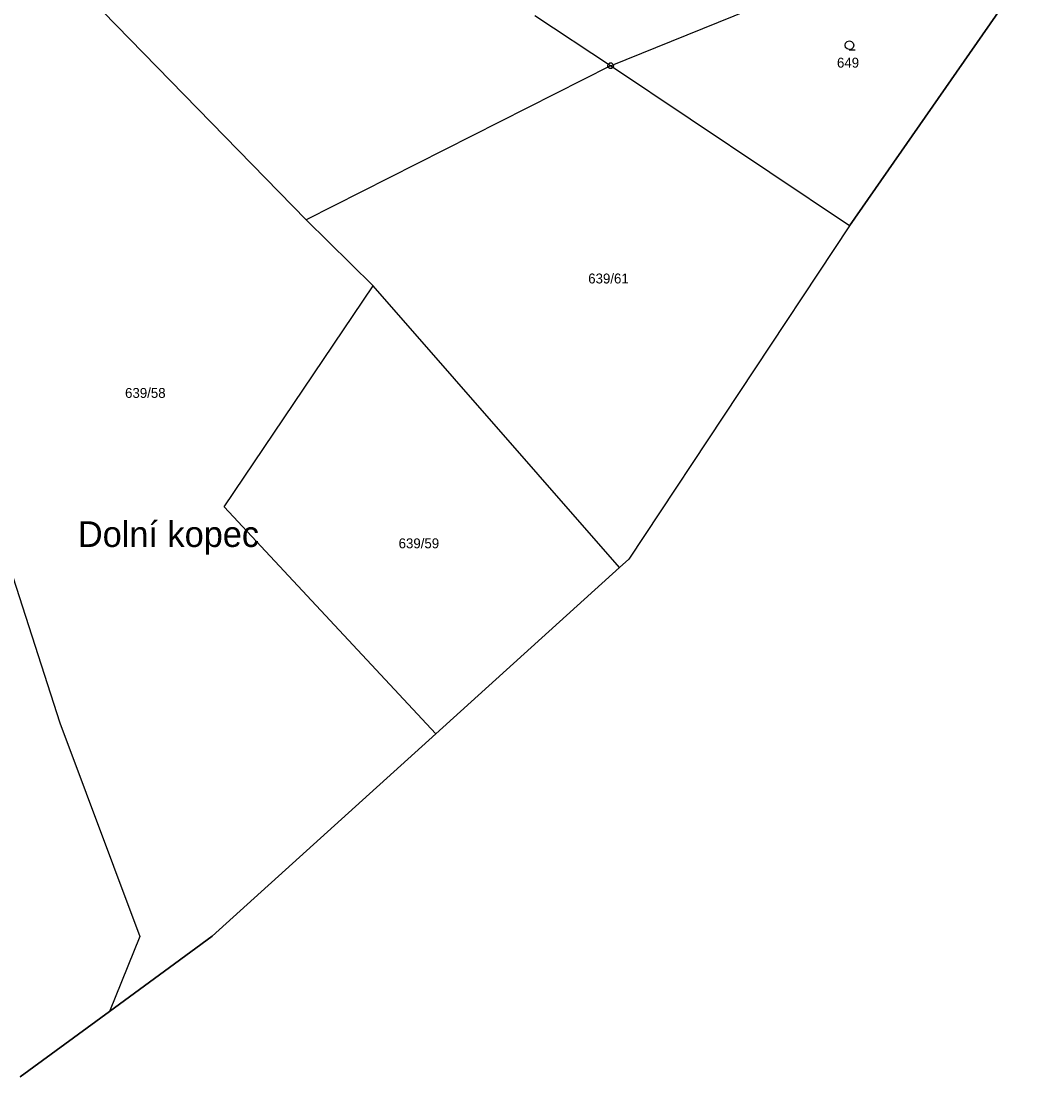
# Model space of a CAD drawing. Extents: x -759699 to -757730, y -1172308 to -1170857.
# Drawn here: x -758550 to -758376.9, y -1171577.6 to -1171396.5 of the extents above; entities that cross this region are included whole.
import ezdxf

# ---------------------------------------------------------------- set-up
doc = ezdxf.new("R2010")
doc.units = 0
for name, color, linetype in [('Vrstva 1', 7, 'Continuous'), ('Vrstva 11', 7, 'Continuous'), ('Vrstva 2', 7, 'Continuous'), ('Vrstva 3', 7, 'Continuous'), ('Vrstva 7', 7, 'Continuous'), ('Vrstva 8', 7, 'Continuous')]:
    doc.layers.add(name, color=color, linetype=linetype)

msp = doc.modelspace()

# ---------------------------------------------------------------- linework, layer by layer
at = {"layer": 'Vrstva 1'}
for p, q in [((-758501.09, -1171430.59), (-758549.8, -1171380.61)), ((-758448.84, -1171404.15), (-758397.71, -1171383.44)), ((-758407.85, -1171431.61), (-758376.92, -1171387.14)), ((-758448.84, -1171404.15), (-758461.83, -1171395.59)), ((-758448.84, -1171404.15), (-758501.09, -1171430.59)), ((-758407.85, -1171431.61), (-758448.84, -1171404.15)), ((-758501.09, -1171430.59), (-758489.58, -1171441.92)), ((-758407.85, -1171431.61), (-758445.74, -1171488.79)), ((-758515.17, -1171479.82), (-758489.58, -1171441.92)), ((-758447.31, -1171490.21), (-758489.58, -1171441.92)), ((-758562.96, -1171456.1), (-758543.32, -1171516.87)), ((-758478.81, -1171518.72), (-758515.17, -1171479.82)), ((-758447.31, -1171490.21), (-758445.74, -1171488.79)), ((-758478.81, -1171518.72), (-758447.31, -1171490.21)), ((-758543.32, -1171516.87), (-758529.61, -1171553.52)), ((-758517.19, -1171553.46), (-758478.81, -1171518.72)), ((-758529.61, -1171553.52), (-758534.83, -1171566.37)), ((-758524.54, -1171558.84), (-758517.19, -1171553.46)), ((-758534.83, -1171566.37), (-758524.54, -1171558.84)), ((-758550.16, -1171577.59), (-758534.83, -1171566.37))]:
    msp.add_line(p, q, dxfattribs=at)
at = {"layer": 'Vrstva 11'}
for p, q in [((-758376.92, -1171387.14), (-758407.85, -1171431.61)), ((-758407.85, -1171431.61), (-758445.74, -1171488.79)), ((-758445.74, -1171488.79), (-758447.31, -1171490.21)), ((-758447.31, -1171490.21), (-758478.81, -1171518.72)), ((-758478.81, -1171518.72), (-758517.19, -1171553.46)), ((-758517.19, -1171553.46), (-758524.54, -1171558.84)), ((-758524.54, -1171558.84), (-758534.83, -1171566.37)), ((-758534.83, -1171566.37), (-758550.16, -1171577.59))]:
    msp.add_line(p, q, dxfattribs=at)
at = {"layer": 'Vrstva 3'}
msp.add_lwpolyline([(-758407.88, -1171401.37), (-758408.26, -1171401.27), (-758408.53, -1171401), (-758408.63, -1171400.63), (-758408.53, -1171400.26), (-758408.26, -1171399.99), (-758407.89, -1171399.89), (-758407.52, -1171399.99), (-758407.25, -1171400.26), (-758407.15, -1171400.64), (-758407.25, -1171401.02), (-758407.52, -1171401.29), (-758407.9, -1171401.39), (-758406.9, -1171401.39)], dxfattribs=at)
at = {"layer": 'Vrstva 8'}
msp.add_line((-758448.96, -1171404.15), (-758448.72, -1171404.15), dxfattribs=at)
msp.add_lwpolyline([(-758448.69, -1171403.67), (-758448.44, -1171403.85), (-758448.34, -1171404.14), (-758448.44, -1171404.43), (-758448.69, -1171404.61), (-758449, -1171404.61), (-758449.25, -1171404.43), (-758449.35, -1171404.14), (-758449.25, -1171403.85), (-758449, -1171403.67)], close=True, dxfattribs=at)

# ---------------------------------------------------------------- texts
at = {"layer": 'Vrstva 2'}
for s, p in [('649', (-758410.014, -1171404.47)), ('639/61', (-758452.691, -1171441.49)), ('639/58', (-758532.146, -1171461.12)), ('639/59', (-758485.216, -1171486.92))]:
    msp.add_text(s, height=1.7, dxfattribs=at).set_placement(p)
at = {"layer": 'Vrstva 7'}
msp.add_text('Dolní kopec', height=4.4, dxfattribs=at).set_placement((-758540.236, -1171486.69))

doc.saveas('drawing.dxf')
